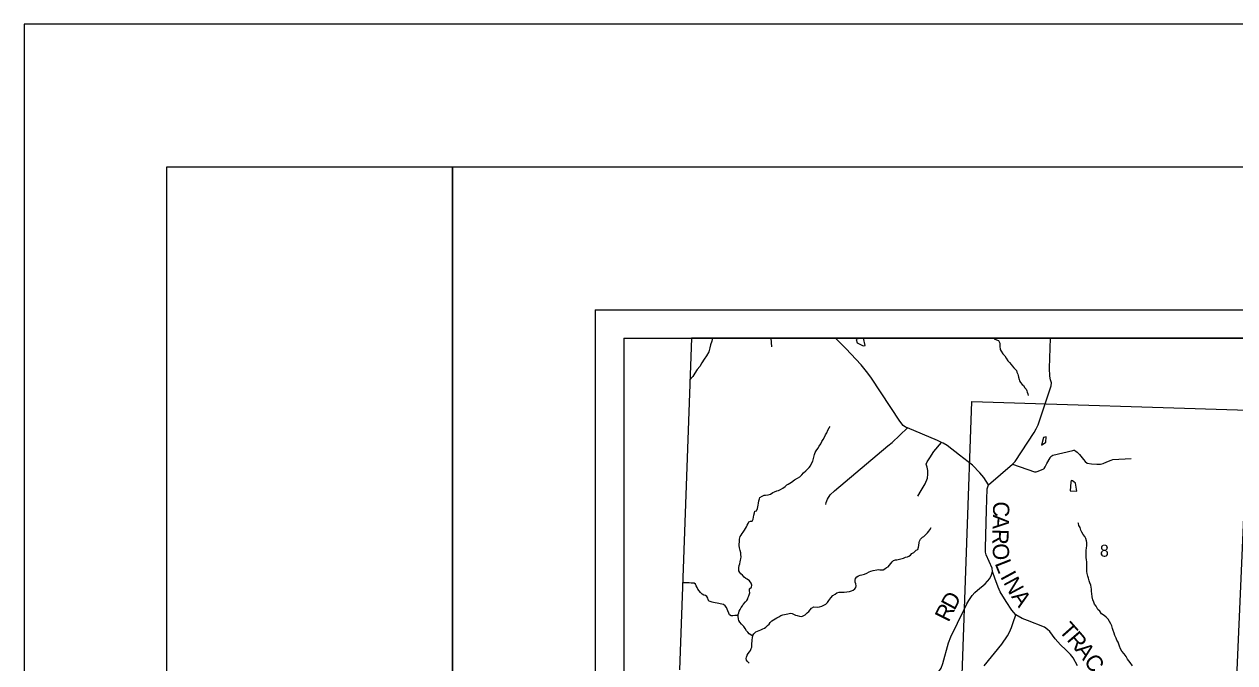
# Model space of a CAD drawing. Extents: x -7.5 to 26.5, y 3.5 to 25.5.
# Drawn here: x -7.457 to -3.216, y 23.263 to 25.5 of the extents above; entities that cross this region are included whole.
import ezdxf

# ---------------------------------------------------------------- set-up
doc = ezdxf.new("R2010")
doc.units = 0
for name, color, linetype in [('GM_X_Corporation', 7, 'Continuous'), ('GM_X_County_Road', 7, 'Continuous'), ('GM_X_County_Road_Text', 7, 'Continuous'), ('GM_X_Minor_River', 7, 'Continuous'), ('GM_X_Section_Text', 7, 'Continuous'), ('GM_X_Township_Road', 7, 'Continuous'), ('SH_Border', 7, 'Continuous'), ('SH_Cut_Line', 7, 'Continuous'), ('SH_Data', 7, 'Continuous')]:
    doc.layers.add(name, color=color, linetype=linetype)

msp = doc.modelspace()

# ---------------------------------------------------------------- linework, layer by layer
at = {"layer": 'GM_X_Corporation'}
for points in [[(1.4431, 24.4), (-5.1194, 24.4), (-5.1615, 23.2384)], [(-2.1213, 24.4), (-5.1194, 24.4), (-5.1615, 23.2384)]]:
    msp.add_lwpolyline(points, dxfattribs=at)
msp.add_lwpolyline([(-4.138, 24.1781), (-3.1693, 24.148), (-3.2132, 23.1565), (-4.1729, 23.1886)], close=True, dxfattribs=at)
at = {"layer": 'GM_X_County_Road'}
for points in [[(-4.079, 23.8872), (-4.096, 23.9125), (-4.1099, 23.9289), (-4.1356, 23.9552), (-4.1804, 23.9906), (-4.2234, 24.0239), (-4.2382, 24.0328), (-4.2434, 24.035), (-4.2581, 24.0414), (-4.3631, 24.086), (-4.3696, 24.0888), (-4.3782, 24.0944), (-4.3899, 24.1092), (-4.4889, 24.2604), (-4.502, 24.2775), (-4.5254, 24.3068), (-4.5789, 24.3644), (-4.6149, 24.4)], [(-4.079, 23.8872), (-3.9949, 23.9588), (-3.9856, 23.9685), (-3.9193, 24.0694), (-3.912, 24.0828), (-3.9055, 24.0967), (-3.8593, 24.2335), (-3.8586, 24.2434), (-3.8616, 24.2541), (-3.8639, 24.2667), (-3.8652, 24.2949), (-3.8625, 24.4)], [(-4.0648, 23.5832), (-4.0664, 23.5943), (-4.0871, 23.6412), (-4.0898, 23.6504), (-4.0897, 23.666), (-4.0865, 23.7974), (-4.0841, 23.873), (-4.079, 23.8872)], [(-4.3557, 23.0673), (-4.3318, 23.1095), (-4.3115, 23.1487), (-4.2883, 23.1867), (-4.2592, 23.2222), (-4.2527, 23.2325), (-4.2455, 23.245), (-4.239, 23.2613), (-4.2197, 23.3335), (-4.2114, 23.3542), (-4.165, 23.4496), (-4.1546, 23.4697), (-4.148, 23.482), (-4.1366, 23.4992), (-4.1272, 23.5096), (-4.1173, 23.5179), (-4.0908, 23.54), (-4.0744, 23.5582), (-4.0689, 23.5712), (-4.0648, 23.5832)], [(-3.768, 23.2524), (-3.7825, 23.2807), (-3.7922, 23.2926), (-3.8085, 23.3089), (-3.8269, 23.3257), (-3.8461, 23.3475), (-3.8645, 23.3734), (-3.8727, 23.3803), (-3.8834, 23.3878), (-3.942, 23.4109), (-3.9614, 23.4188), (-3.9833, 23.4311), (-3.9976, 23.4473), (-4.0178, 23.4785), (-4.0379, 23.5117), (-4.0459, 23.5279), (-4.0574, 23.5598), (-4.0648, 23.5832)], [(-4.0945, 23.253), (-4.0327, 23.3282), (-4.0129, 23.3578), (-4.0055, 23.371), (-3.9986, 23.3872), (-3.9929, 23.4043), (-3.9833, 23.4311)]]:
    msp.add_lwpolyline(points, dxfattribs=at)
at = {"layer": 'GM_X_Minor_River'}
msp.add_line((-4.5111, 24.375), (-4.5176, 24.4), dxfattribs=at)
for points in [[(-5.0457, 24.4), (-5.0487, 24.3895), (-5.0524, 24.3774), (-5.055, 24.3661), (-5.0587, 24.3528), (-5.0667, 24.3382), (-5.0749, 24.3262), (-5.0832, 24.3135), (-5.0903, 24.3008), (-5.0993, 24.2903), (-5.1076, 24.278), (-5.1154, 24.266), (-5.126, 24.2537)], [(-4.535, 24.4), (-4.5367, 24.3985), (-4.5428, 24.3956), (-4.5393, 24.3841), (-4.5187, 24.3737), (-4.5111, 24.375)], [(-4.0597, 24.4), (-4.059, 24.3984), (-4.0515, 24.3947), (-4.0443, 24.3922), (-4.0396, 24.3834), (-4.0394, 24.3777), (-4.0392, 24.3723), (-4.0384, 24.3609), (-4.0348, 24.3544), (-4.0293, 24.3458), (-4.0216, 24.3384), (-4.0168, 24.3307), (-4.011, 24.3214), (-4.0051, 24.3151), (-4, 24.3081), (-3.9967, 24.3031), (-3.9901, 24.2961), (-3.9853, 24.2921), (-3.9816, 24.2867), (-3.9795, 24.2813), (-3.9767, 24.2744), (-3.9749, 24.2694), (-3.9739, 24.2637), (-3.9715, 24.256), (-3.9705, 24.251), (-3.9673, 24.2445), (-3.9617, 24.2386), (-3.9569, 24.2347), (-3.9514, 24.2265), (-3.9478, 24.2215), (-3.9449, 24.2161)], [(-3.9449, 24.2161), (-3.9435, 24.2107), (-3.9414, 24.205), (-3.9401, 24.1996)], [(-4.7079, 23.9478), (-4.7031, 23.9537), (-4.6991, 23.9608), (-4.6943, 23.969), (-4.6917, 23.9784), (-4.6908, 23.9837), (-4.689, 23.9924), (-4.6869, 24.0003), (-4.6825, 24.0055), (-4.6769, 24.0144), (-4.6721, 24.0222), (-4.6669, 24.0308), (-4.6625, 24.0379), (-4.6589, 24.0453), (-4.6533, 24.0535), (-4.6497, 24.0614), (-4.646, 24.0685), (-4.6415, 24.0778), (-4.6371, 24.086), (-4.6339, 24.0909)], [(-3.8767, 24.0544), (-3.8867, 24.0523), (-3.8934, 24.0259)], [(-3.8934, 24.0259), (-3.878, 24.0358), (-3.8767, 24.0544)], [(-4.9049, 23.357), (-4.9181, 23.3648), (-4.9221, 23.3703), (-4.9272, 23.3757), (-4.9316, 23.3831), (-4.9367, 23.3904), (-4.9441, 23.399), (-4.9499, 23.4057), (-4.954, 23.4115), (-4.955, 23.4164), (-4.9558, 23.4267), (-4.9556, 23.432), (-4.9543, 23.4384), (-4.9526, 23.4441), (-4.9494, 23.4504), (-4.9457, 23.4571), (-4.9414, 23.4627), (-4.9386, 23.4676), (-4.9307, 23.4764), (-4.9256, 23.4816), (-4.9227, 23.4879), (-4.9207, 23.4928), (-4.9182, 23.4981), (-4.9149, 23.5086), (-4.9162, 23.5158), (-4.916, 23.5219), (-4.9097, 23.5285), (-4.908, 23.5349), (-4.91, 23.5426), (-4.9167, 23.5504), (-4.9241, 23.5559), (-4.9297, 23.5591), (-4.9353, 23.5631), (-4.9412, 23.5701), (-4.9468, 23.5748), (-4.9504, 23.5799), (-4.9537, 23.5853), (-4.9543, 23.5903), (-4.9537, 23.5963), (-4.9524, 23.6035), (-4.9503, 23.6095), (-4.9485, 23.6166), (-4.9476, 23.6227), (-4.9467, 23.6276), (-4.9457, 23.6348), (-4.9462, 23.6431), (-4.9465, 23.6481), (-4.9485, 23.6569), (-4.9512, 23.6664), (-4.9521, 23.6741), (-4.9516, 23.6911), (-4.9511, 23.696), (-4.9502, 23.701), (-4.9485, 23.7058), (-4.9457, 23.7107), (-4.9418, 23.7159), (-4.9382, 23.7211), (-4.9342, 23.7278), (-4.9309, 23.7341), (-4.9273, 23.7393), (-4.9241, 23.7449), (-4.9216, 23.7517), (-4.9184, 23.7565), (-4.913, 23.7594), (-4.9066, 23.7596), (-4.9037, 23.7663), (-4.9027, 23.7731), (-4.9017, 23.7803), (-4.8992, 23.789), (-4.8975, 23.7942), (-4.8918, 23.7952), (-4.8889, 23.8034), (-4.8859, 23.8151), (-4.8845, 23.8227), (-4.8831, 23.8306), (-4.8818, 23.837), (-4.8801, 23.8419), (-4.8723, 23.8473), (-4.8654, 23.8505), (-4.8604, 23.8508), (-4.8513, 23.8516), (-4.8428, 23.854), (-4.8346, 23.8595), (-4.8285, 23.8616), (-4.8204, 23.8651), (-4.8142, 23.8668), (-4.8081, 23.8697), (-4.7999, 23.8755), (-4.7918, 23.8802), (-4.7859, 23.8864), (-4.7805, 23.8885), (-4.775, 23.8929), (-4.7692, 23.8965), (-4.7587, 23.9038), (-4.7482, 23.9099), (-4.7401, 23.915), (-4.7334, 23.9212), (-4.7267, 23.9283), (-4.7193, 23.9356), (-4.7126, 23.9426), (-4.7079, 23.9478)], [(-3.775, 23.8924), (-3.7798, 23.8971), (-3.785, 23.9007), (-3.7895, 23.9015), (-3.7912, 23.8959), (-3.7927, 23.8659), (-3.7692, 23.8641)], [(-3.7692, 23.8641), (-3.775, 23.8924)], [(-3.5747, 23.2528), (-3.5827, 23.2645), (-3.5918, 23.2758), (-3.5972, 23.2851), (-3.6041, 23.2945), (-3.6122, 23.3035), (-3.6164, 23.312), (-3.6203, 23.3213), (-3.6227, 23.3282), (-3.6255, 23.3351), (-3.6291, 23.3425), (-3.6319, 23.349), (-3.6365, 23.3591), (-3.6389, 23.3668), (-3.642, 23.3768), (-3.6445, 23.3833), (-3.6476, 23.3922), (-3.6511, 23.3999), (-3.6554, 23.4084), (-3.6605, 23.4158), (-3.6674, 23.4232), (-3.6744, 23.4292), (-3.683, 23.4348), (-3.6895, 23.4437), (-3.6962, 23.4497), (-3.7026, 23.4613), (-3.7077, 23.4683), (-3.7105, 23.476), (-3.714, 23.4841), (-3.716, 23.4941), (-3.7175, 23.5055), (-3.718, 23.5135), (-3.7181, 23.5208), (-3.719, 23.528), (-3.7211, 23.5349), (-3.7242, 23.5434), (-3.7263, 23.5499), (-3.7294, 23.5592), (-3.7314, 23.5672), (-3.7334, 23.576), (-3.7346, 23.5833), (-3.7348, 23.5898), (-3.7353, 23.5974), (-3.7346, 23.6069), (-3.7351, 23.6168), (-3.7363, 23.6244), (-3.7372, 23.6325), (-3.7372, 23.6427), (-3.7374, 23.6503), (-3.7367, 23.6579), (-3.7357, 23.6651), (-3.7347, 23.6746), (-3.7347, 23.6841), (-3.7357, 23.691), (-3.7384, 23.6983), (-3.742, 23.706), (-3.7475, 23.7131), (-3.7518, 23.7204), (-3.7553, 23.7274), (-3.7581, 23.7366), (-3.7624, 23.7436), (-3.7644, 23.7509), (-3.7653, 23.753)], [(-4.4835, 23.5871), (-4.4705, 23.589), (-4.4651, 23.5896), (-4.4598, 23.5894), (-4.4537, 23.5889), (-4.4484, 23.5891), (-4.4418, 23.5923), (-4.4364, 23.5967), (-4.4309, 23.5999), (-4.4258, 23.6047), (-4.4211, 23.6106), (-4.4167, 23.617), (-4.4116, 23.6214), (-4.4051, 23.6234), (-4.4001, 23.6244), (-4.3859, 23.6278), (-4.3775, 23.6302), (-4.3694, 23.6333), (-4.3633, 23.6347), (-4.3579, 23.6364), (-4.352, 23.6408), (-4.3477, 23.6456), (-4.3404, 23.6491), (-4.3321, 23.6572), (-4.3263, 23.6605), (-4.3242, 23.6684), (-4.3229, 23.6736), (-4.3218, 23.6842), (-4.3213, 23.6892), (-4.3172, 23.6966), (-4.3105, 23.7036), (-4.3052, 23.7057), (-4.2989, 23.7124), (-4.293, 23.7183), (-4.2878, 23.7246), (-4.2846, 23.7294), (-4.2799, 23.7368)], [(-4.9173, 23.2619), (-4.9237, 23.2675), (-4.9273, 23.2729), (-4.9279, 23.2786), (-4.927, 23.2835), (-4.9245, 23.2903), (-4.9209, 23.2958), (-4.9158, 23.3014), (-4.913, 23.3062), (-4.9101, 23.3133), (-4.9084, 23.3186), (-4.9078, 23.3254), (-4.9077, 23.3307), (-4.907, 23.3387), (-4.9065, 23.3447), (-4.9059, 23.35), (-4.9045, 23.3591), (-4.9017, 23.3647), (-4.8943, 23.3713), (-4.8885, 23.3745), (-4.8823, 23.3766), (-4.8769, 23.3787), (-4.8696, 23.3827), (-4.8638, 23.3848), (-4.8587, 23.3884), (-4.8529, 23.3936), (-4.8474, 23.3991), (-4.8434, 23.4039), (-4.8383, 23.4098), (-4.8328, 23.4142), (-4.827, 23.4174), (-4.8201, 23.421), (-4.8135, 23.4242), (-4.8069, 23.4286), (-4.8, 23.431), (-4.7885, 23.4337), (-4.7823, 23.4347), (-4.7773, 23.436), (-4.7724, 23.4366), (-4.7674, 23.4361), (-4.7547, 23.4304), (-4.749, 23.4291), (-4.7418, 23.427), (-4.7358, 23.4253), (-4.7308, 23.4266), (-4.7208, 23.4309), (-4.7141, 23.4386), (-4.7086, 23.4426), (-4.7039, 23.4489), (-4.6987, 23.4552), (-4.6914, 23.4588), (-4.6784, 23.4584), (-4.6712, 23.4597), (-4.6635, 23.4617), (-4.6562, 23.4646), (-4.6492, 23.4685), (-4.6437, 23.474), (-4.6385, 23.4815), (-4.6314, 23.4911), (-4.6239, 23.4985), (-4.6165, 23.5039), (-4.61, 23.5079), (-4.6026, 23.5107), (-4.5962, 23.5109), (-4.5848, 23.5106), (-4.576, 23.5114), (-4.566, 23.5134), (-4.5591, 23.5151), (-4.5533, 23.5172), (-4.5471, 23.5223), (-4.5443, 23.5275), (-4.5422, 23.5332), (-4.5439, 23.5397), (-4.546, 23.5462), (-4.5466, 23.5526), (-4.5449, 23.5583), (-4.5405, 23.5638), (-4.5343, 23.5682), (-4.5285, 23.5703), (-4.5232, 23.5713), (-4.5139, 23.574), (-4.5058, 23.5776), (-4.4977, 23.5815), (-4.4908, 23.5847), (-4.4835, 23.5871)], [(-4.9557, 23.4295), (-4.9683, 23.429), (-4.9744, 23.428), (-4.9809, 23.4282), (-4.9865, 23.4318), (-4.9886, 23.4368), (-4.9918, 23.4449), (-4.9946, 23.4511), (-4.9968, 23.4568), (-5.0011, 23.4627), (-5.0071, 23.4674), (-5.0128, 23.4683), (-5.0188, 23.4696), (-5.0241, 23.4706), (-5.0298, 23.4719), (-5.0366, 23.4732), (-5.0419, 23.4749), (-5.0468, 23.4754), (-5.0536, 23.4779), (-5.0593, 23.4792), (-5.0614, 23.485), (-5.0624, 23.49), (-5.0653, 23.4957), (-5.0705, 23.4986), (-5.0765, 23.5006), (-5.0818, 23.5031), (-5.0885, 23.509), (-5.0932, 23.5152), (-5.0972, 23.5214), (-5.1001, 23.5268), (-5.103, 23.533), (-5.1054, 23.5387), (-5.1103, 23.5419), (-5.1206, 23.5422), (-5.1274, 23.5428), (-5.1396, 23.5432), (-5.1497, 23.5437)]]:
    msp.add_lwpolyline(points, dxfattribs=at)
at = {"layer": 'GM_X_Township_Road'}
msp.add_line((-4.8379, 24.3701), (-4.8405, 24.4), dxfattribs=at)
for points in [[(-4.6488, 23.8182), (-4.6478, 23.825), (-4.6437, 23.8359), (-4.6337, 23.8512), (-4.6191, 23.8659), (-4.4322, 24.0228), (-4.4162, 24.0352), (-4.3631, 24.086)], [(-4.3262, 23.8469), (-4.3156, 23.867), (-4.3014, 23.8906), (-4.2932, 23.9095), (-4.2914, 23.924), (-4.2914, 23.9364), (-4.2943, 23.9485), (-4.2973, 23.9588), (-4.2943, 23.9674), (-4.2849, 23.9807), (-4.2707, 24.0028), (-4.2434, 24.035)], [(-3.9949, 23.9588), (-3.9177, 23.9325), (-3.9124, 23.9327), (-3.9052, 23.9343), (-3.8909, 23.9407), (-3.8859, 23.9428), (-3.8842, 23.9444), (-3.8807, 23.9491), (-3.875, 23.9611), (-3.8637, 23.9816), (-3.8606, 23.9861), (-3.8536, 23.9908), (-3.7843, 24.0071), (-3.7808, 24.0078), (-3.7791, 24.0078), (-3.7781, 24.0075), (-3.7771, 24.0069), (-3.7727, 24.0042), (-3.7681, 24.0005), (-3.7601, 23.993), (-3.7467, 23.9751), (-3.7408, 23.9684), (-3.7334, 23.9625), (-3.7179, 23.9601), (-3.6993, 23.9595)], [(-3.6993, 23.9595), (-3.6868, 23.959), (-3.6776, 23.9618), (-3.6642, 23.9674), (-3.6495, 23.973), (-3.6434, 23.9751), (-3.5791, 23.9794)]]:
    msp.add_lwpolyline(points, dxfattribs=at)
at = {"layer": 'SH_Border'}
for points in [[(-6.9569, 25), (-5.9569, 25), (-5.9569, 4), (-6.9569, 4)], [(-5.9569, 25), (26.0431, 25), (26.0431, 4), (-5.9569, 4)]]:
    msp.add_lwpolyline(points, close=True, dxfattribs=at)
at = {"layer": 'SH_Cut_Line'}
msp.add_lwpolyline([(-7.4569, 3.5), (26.5431, 3.5), (26.5431, 25.5), (-7.4569, 25.5)], close=True, dxfattribs=at)
at = {"layer": 'SH_Data'}
for p, q in [((-5.4569, 24.5), (1.5431, 24.5)), ((-5.4569, 24.5), (-5.4569, 17.5)), ((-5.3569, 24.4), (-5.3569, 17.6)), ((-5.3569, 24.4), (1.4431, 24.4))]:
    msp.add_line(p, q, dxfattribs=at)

# ---------------------------------------------------------------- texts
at = {"layer": 'GM_X_County_Road_Text'}
for s, rotation, p in [('C', 268.3715, (-4.0623, 23.8292)), ('A', 268.3718, (-4.0637, 23.7826)), ('R', 268.5847, (-4.0651, 23.7324)), ('O', 274.4164, (-4.0661, 23.6794)), ('L', 291.5217, (-4.0581, 23.6116)), ('I', 298.4698, (-4.0393, 23.5652)), ('N', 298.2852, (-4.0282, 23.5447)), ('D', 61.8611, (-4.1984, 23.4445)), ('A', 304.6004, (-4.001, 23.4949)), ('R', 63.6856, (-4.2189, 23.4031)), ('T', 311.4818, (-3.8354, 23.3746)), ('R', 310.8641, (-3.8074, 23.3429)), ('A', 307.6209, (-3.7774, 23.3083)), ('C', 305.0159, (-3.7473, 23.2692))]:
    msp.add_text(s, height=0.0568, rotation=rotation, dxfattribs=at).set_placement(p)
at = {"layer": 'GM_X_Section_Text'}
msp.add_text('8', height=0.0419, rotation=0, dxfattribs=at).set_placement((-3.6888, 23.6349))

doc.saveas('drawing.dxf')
